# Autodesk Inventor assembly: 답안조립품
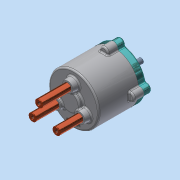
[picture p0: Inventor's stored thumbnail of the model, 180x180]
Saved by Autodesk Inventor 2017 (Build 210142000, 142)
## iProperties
Part Number: 답안조립품
Material: 일반
Document SubType Name: Assembly
Designer: MRC
Mass: 1236.63 g
Surface Area: 1770.11 cm^2
Volume: 433.79 cm^3
Density: 2.85076 g/cm^3
Author: MRC
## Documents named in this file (14)
- C:\Users\MRC\Desktop\610708V1003\답안조립품.iam
- C:\Users\MRC\Desktop\610708V1003\본체.ipt
- C:\Users\MRC\Desktop\610708V1003\가변스프링-01.ipt
- C:\Users\MRC\Desktop\610708V1003\가변스프링-02.ipt
- C:\Users\MRC\Desktop\610708V1003\가변스프링-03.ipt
- C:\Users\MRC\Desktop\610708V1003\멈춤링 10 x 1.ipt
- C:\Users\MRC\Desktop\610708V1003\멈춤링 22 x 1.2.ipt
- C:\Users\MRC\Desktop\610708V1003\메인 축.ipt
- C:\Users\MRC\Desktop\610708V1003\베어링 NA 4900.ipt
- C:\Users\MRC\Desktop\610708V1003\볼트 M5.ipt
- C:\Users\MRC\Desktop\610708V1003\슬라이드 축.ipt
- C:\Users\MRC\Desktop\610708V1003\오일실.ipt
- C:\Users\MRC\Desktop\610708V1003\커버.ipt
- C:\Users\MRC\Desktop\610708V1003\판캠.ipt
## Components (3 placed, 3 different names)
1. 가변스프링-01:1
2. 가변스프링-02:1
3. 가변스프링-03:1
